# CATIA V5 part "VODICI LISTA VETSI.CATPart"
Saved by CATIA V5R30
Part number: VODICI LISTA VETSI
Bounding box of the stored display mesh (mm): x -50 to 50, y 0 to 19, z -8 to 12
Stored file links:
  C:\Users\ondra\Desktop\PŘÍLOHA P III\CATIA\VODICI LISTA VETSI.CATPart
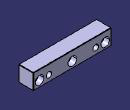
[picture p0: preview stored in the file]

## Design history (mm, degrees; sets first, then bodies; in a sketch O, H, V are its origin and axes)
Set1
  DatumSurface1 to DatumSurface43 "Z1850/20"
  Plane1: type Tangent, Support DatumSurface23, RefPoint vertex [face of DatumSurface11]
  Plane2: type Tangent, Support DatumSurface13, RefPoint vertex [face of DatumSurface11]
  Plane3: type Tangent, Support DatumSurface43, RefPoint vertex [face of DatumSurface43]
  Plane4: type Tangent, Support DatumSurface13, RefPoint vertex [face of DatumSurface13]
  Plane5: type Tangent, Support DatumSurface20, RefPoint vertex [face of DatumSurface18]
  Point1: type OnSurface, Support DatumSurface40, Length 0, Direction edge of DatumSurface41
  Plane6: type Tangent, Support DatumSurface40, RefPoint Point1
  Plane7: type Tangent, Support DatumSurface27, RefPoint vertex [face of DatumSurface14]
  Plane8: type Offset, RefPlane Plane7, Offset 1, reversed
  Join1: Elements (DatumSurface1; DatumSurface2; DatumSurface3; DatumSurface4; DatumSurface5; DatumSurface6; DatumSurface7; DatumSurface8; DatumSurface9; DatumSurface10; DatumSurface11; DatumSurface12; DatumSurface13; DatumSurface14; DatumSurface15; DatumSurface16; DatumSurface17; DatumSurface18; DatumSurface19; DatumSurface20; DatumSurface21; DatumSurface22; DatumSurface23; DatumSurface24; DatumSurface25; DatumSurface26; DatumSurface27; DatumSurface28; DatumSurface29; DatumSurface30; DatumSurface31; DatumSurface32; DatumSurface33; DatumSurface34; DatumSurface35; DatumSurface36; DatumSurface37; DatumSurface38; DatumSurface39; DatumSurface40; DatumSurface41; DatumSurface42; DatumSurface43)
Body1 (main body)
  CloseSurface1: CloseElement Join1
